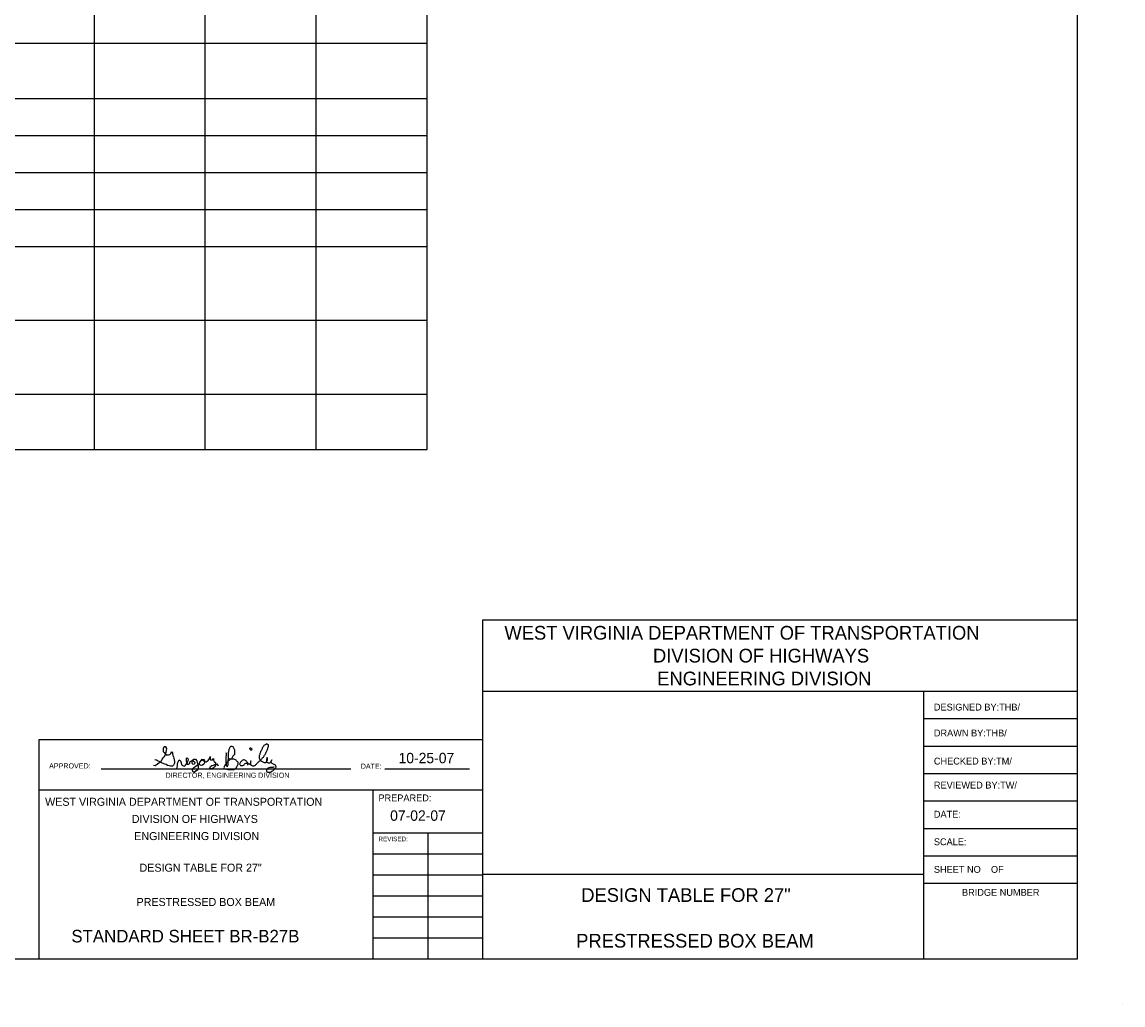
# Model space of a CAD drawing. Extents: x 762.3 to 790.4, y -1210.3 to -1192.2.
# Drawn here: x 780.44 to 790.37, y -1210.35 to -1201.48 of the extents above; entities that cross this region are included whole.
import ezdxf

# ---------------------------------------------------------------- set-up
doc = ezdxf.new("R2010")
doc.units = 0
doc.layers.add('Default', color=7, linetype='Continuous')
doc.layers.add('Level 1', color=7, linetype='Continuous')

msp = doc.modelspace()

# ---------------------------------------------------------------- linework, layer by layer
at = {"layer": 'Default'}
for p, q in [((789.9542, -1192.6096), (789.9542, -1209.9346)), ((781.0909, -1202.1689), (781.0909, -1201.1689)), ((782.0909, -1202.1689), (782.0909, -1201.1689)), ((783.0909, -1202.1689), (783.0909, -1201.1689)), ((784.0909, -1202.1689), (784.0909, -1201.1689)), ((764.5075, -1201.6689), (784.0909, -1201.6689)), ((764.5075, -1202.1689), (784.0909, -1202.1689)), ((781.0909, -1205.3356), (781.0909, -1202.1689)), ((782.0909, -1205.3356), (782.0909, -1202.1689)), ((783.0909, -1205.3356), (783.0909, -1202.1689)), ((784.0909, -1205.3356), (784.0909, -1202.1689)), ((766.2575, -1202.5023), (784.0909, -1202.5023)), ((766.2575, -1202.8356), (784.0909, -1202.8356)), ((764.5075, -1203.1689), (784.0909, -1203.1689)), ((766.2575, -1203.5023), (784.0909, -1203.5023)), ((766.2575, -1204.1689), (784.0909, -1204.1689)), ((764.5075, -1204.8356), (784.0909, -1204.8356)), ((764.5075, -1205.3356), (784.0909, -1205.3356)), ((789.9542, -1206.8755), (784.5917, -1206.8755)), ((784.5917, -1206.8755), (784.5917, -1209.9346)), ((784.5917, -1206.9415), (784.5917, -1206.9415)), ((789.9542, -1206.9415), (789.9542, -1206.9415)), ((788.5682, -1207.519), (784.5917, -1207.519)), ((788.5682, -1207.519), (788.5682, -1209.9346)), ((789.9542, -1207.519), (788.5682, -1207.519)), ((789.9542, -1207.7665), (788.5682, -1207.7665)), ((784.5917, -1207.9546), (780.5905, -1207.9546)), ((780.5905, -1207.9546), (780.5905, -1209.9346)), ((784.5917, -1207.9546), (784.5917, -1207.9546)), ((789.9542, -1208.014), (788.5682, -1208.014)), ((781.152, -1208.2157), (783.4022, -1208.2157)), ((783.7105, -1208.2157), (784.4725, -1208.2157)), ((789.9542, -1208.2615), (788.5682, -1208.2615)), ((783.6017, -1208.4083), (780.5905, -1208.4083)), ((783.6017, -1208.4083), (783.6017, -1209.9346)), ((784.5917, -1208.4083), (783.6017, -1208.4083)), ((789.9542, -1208.509), (788.5682, -1208.509)), ((784.5917, -1208.7961), (783.6017, -1208.7961)), ((784.0967, -1208.7961), (784.0967, -1209.9346)), ((789.9542, -1208.7565), (788.5682, -1208.7565)), ((784.5917, -1208.9858), (783.6017, -1208.9858)), ((789.9542, -1209.004), (788.5682, -1209.004)), ((784.5917, -1209.1756), (783.6017, -1209.1756)), ((788.5682, -1209.169), (784.5917, -1209.169)), ((789.9542, -1209.2515), (788.5682, -1209.2515)), ((784.5917, -1209.3653), (783.6017, -1209.3653)), ((784.5917, -1209.5551), (783.6017, -1209.5551)), ((784.5917, -1209.7448), (783.6017, -1209.7448)), ((789.9542, -1209.9346), (763.5542, -1209.9346)), ((784.5917, -1209.9346), (784.5917, -1209.9346)), ((784.5917, -1209.9346), (784.5917, -1209.9346)), ((789.9542, -1209.9115), (789.9542, -1209.9115)), ((789.9542, -1209.9346), (789.9542, -1209.9346)), ((790.3667, -1210.3471), (790.3667, -1210.3471))]:
    msp.add_line(p, q, dxfattribs=at)
at = {"layer": 'Level 1'}
for points in [[(781.6233, -1208.1826), (781.6383, -1208.1851), (781.648, -1208.1804), (781.6609, -1208.1726), (781.671, -1208.1625), (781.6836, -1208.155), (781.6949, -1208.1437), (781.7011, -1208.1286), (781.7099, -1208.1173), (781.7212, -1208.1073), (781.73, -1208.0947), (781.7363, -1208.0809), (781.7388, -1208.0646), (781.7413, -1208.0495), (781.7426, -1208.0344), (781.7338, -1208.0193), (781.72, -1208.0193), (781.7124, -1208.0306), (781.7099, -1208.0445), (781.7099, -1208.0595), (781.72, -1208.0696), (781.7288, -1208.0821), (781.7413, -1208.0897), (781.7577, -1208.0909), (781.7715, -1208.0884), (781.7803, -1208.0771), (781.7891, -1208.0633), (781.7966, -1208.0683), (781.7941, -1208.0821), (781.7979, -1208.096), (781.8029, -1208.1085), (781.8079, -1208.1211), (781.8104, -1208.1362), (781.8129, -1208.1512), (781.8129, -1208.1663), (781.8041, -1208.1826), (781.7941, -1208.1927), (781.7778, -1208.1927), (781.7652, -1208.1892), (781.7501, -1208.1851), (781.7376, -1208.1776), (781.725, -1208.1744), (781.7112, -1208.1676), (781.6974, -1208.1625), (781.6861, -1208.155), (781.6735, -1208.15), (781.6609, -1208.1449), (781.6496, -1208.1374), (781.6371, -1208.1349)], [(782.2774, -1208.0696), (782.278, -1208.0765), (782.278, -1208.0834), (782.278, -1208.0903), (782.278, -1208.0978), (782.2767, -1208.1047), (782.2755, -1208.1117), (782.2755, -1208.1186), (782.2755, -1208.1255), (782.2755, -1208.1324), (782.2761, -1208.1393), (782.2767, -1208.1462), (782.2767, -1208.1531), (782.2774, -1208.16), (782.2786, -1208.1669), (782.2793, -1208.1745), (782.2799, -1208.1814), (782.2818, -1208.1883), (782.2862, -1208.1933), (782.2899, -1208.199), (782.2918, -1208.192), (782.2943, -1208.1858), (782.2962, -1208.1789), (782.2968, -1208.1719), (782.2968, -1208.165), (782.2968, -1208.1581), (782.2975, -1208.1512), (782.2975, -1208.1443), (782.2981, -1208.1374), (782.2987, -1208.1305), (782.2994, -1208.1236), (782.2994, -1208.1167), (782.2994, -1208.1098), (782.2994, -1208.1029), (782.2994, -1208.096), (782.2994, -1208.089), (782.2994, -1208.0821), (782.3, -1208.0752), (782.3012, -1208.0683), (782.3025, -1208.0608), (782.3044, -1208.0539), (782.3063, -1208.047), (782.3069, -1208.0401), (782.3094, -1208.0338), (782.3119, -1208.0275), (782.3144, -1208.0212), (782.3182, -1208.0149), (782.3245, -1208.0124), (782.3314, -1208.0131), (782.3383, -1208.0149), (782.3427, -1208.02), (782.3458, -1208.0262), (782.3496, -1208.0319), (782.3527, -1208.0382), (782.354, -1208.0451), (782.3546, -1208.052), (782.3546, -1208.0589), (782.3546, -1208.0658), (782.3546, -1208.0727), (782.3546, -1208.0796), (782.3534, -1208.0865), (782.3496, -1208.0922), (782.3446, -1208.0966), (782.3402, -1208.1016), (782.3377, -1208.1079), (782.3339, -1208.1135), (782.3301, -1208.1192), (782.3276, -1208.1255), (782.322, -1208.1292), (782.3157, -1208.1324), (782.31, -1208.1368), (782.3038, -1208.1405), (782.2987, -1208.1449), (782.2937, -1208.15), (782.2899, -1208.1556), (782.2849, -1208.16), (782.2811, -1208.1657), (782.2774, -1208.1713), (782.2723, -1208.177), (782.2686, -1208.1826), (782.2661, -1208.1889), (782.2623, -1208.1946), (782.2598, -1208.2008), (782.2585, -1208.2077), (782.261, -1208.214), (782.2673, -1208.2165), (782.2742, -1208.2172), (782.2811, -1208.2191), (782.2881, -1208.2203), (782.295, -1208.2209), (782.3019, -1208.2209), (782.3094, -1208.2209), (782.3163, -1208.2209), (782.3232, -1208.2209), (782.3301, -1208.2209), (782.337, -1208.2209), (782.3439, -1208.2209), (782.3509, -1208.2209), (782.3559, -1208.2159), (782.3622, -1208.2134), (782.3678, -1208.2096), (782.3735, -1208.2046), (782.376, -1208.1983), (782.3785, -1208.192), (782.3823, -1208.1864), (782.3848, -1208.1801), (782.3867, -1208.1732), (782.3879, -1208.1663), (782.3879, -1208.1594), (782.3835, -1208.1544), (782.3785, -1208.15), (782.3735, -1208.1449), (782.3691, -1208.1393), (782.3628, -1208.1355), (782.3565, -1208.1318), (782.3496, -1208.1305), (782.3427, -1208.1292), (782.3358, -1208.128), (782.3282, -1208.128), (782.3207, -1208.128), (782.3138, -1208.128), (782.3069, -1208.1267), (782.3069, -1208.1267)], [(782.5933, -1208.1362), (782.5971, -1208.1305), (782.6008, -1208.1248), (782.6046, -1208.1192), (782.609, -1208.1142), (782.6146, -1208.1104), (782.619, -1208.1054), (782.6228, -1208.0991), (782.6259, -1208.0928), (782.6303, -1208.0865), (782.6341, -1208.0803), (782.6366, -1208.074), (782.6404, -1208.0671), (782.6435, -1208.0602), (782.6467, -1208.0532), (782.6492, -1208.047), (782.6517, -1208.0407), (782.6542, -1208.0344), (782.6561, -1208.0275), (782.6586, -1208.0212), (782.6599, -1208.0143), (782.6611, -1208.0074), (782.6599, -1208.0005), (782.6555, -1207.9955), (782.6492, -1207.993), (782.6423, -1207.9917), (782.636, -1207.9955), (782.6303, -1207.9992), (782.6241, -1208.0017), (782.619, -1208.0061), (782.6153, -1208.0118), (782.6115, -1208.0174), (782.6065, -1208.0225), (782.6052, -1208.0294), (782.6027, -1208.0357), (782.6002, -1208.0419), (782.5964, -1208.0476), (782.5939, -1208.0539), (782.5901, -1208.0595), (782.5889, -1208.0664), (782.5851, -1208.0721), (782.5839, -1208.079), (782.5813, -1208.0859), (782.5788, -1208.0928), (782.5763, -1208.0991), (782.5763, -1208.106), (782.5763, -1208.1129), (782.5776, -1208.1198), (782.5807, -1208.1261), (782.5832, -1208.133), (782.5864, -1208.1393), (782.5914, -1208.1437), (782.5977, -1208.1462), (782.6033, -1208.1506), (782.6102, -1208.1519), (782.6165, -1208.1556), (782.6228, -1208.1581), (782.6303, -1208.1588), (782.6372, -1208.1588), (782.641, -1208.1531), (782.6448, -1208.1475), (782.6479, -1208.1405), (782.6504, -1208.1336), (782.6511, -1208.1267), (782.6529, -1208.1192), (782.6479, -1208.1148), (782.6454, -1208.1217), (782.6429, -1208.128), (782.6429, -1208.1349), (782.6429, -1208.1418), (782.6429, -1208.1487), (782.6454, -1208.1556), (782.6517, -1208.1594), (782.658, -1208.1619), (782.6649, -1208.1625), (782.6718, -1208.1625), (782.6781, -1208.16), (782.6818, -1208.1537), (782.6862, -1208.1487), (782.6894, -1208.1418), (782.6913, -1208.1349), (782.6881, -1208.1418), (782.6856, -1208.1481), (782.6831, -1208.1544), (782.6856, -1208.1606), (782.6919, -1208.1638), (782.6982, -1208.1669), (782.7026, -1208.1719), (782.7095, -1208.1738), (782.7164, -1208.1763), (782.7208, -1208.1814), (782.7233, -1208.1877), (782.7258, -1208.1939), (782.7258, -1208.2008), (782.7245, -1208.2077), (782.7195, -1208.2121), (782.7158, -1208.2178), (782.7107, -1208.2234), (782.707, -1208.2291), (782.7007, -1208.2335), (782.6957, -1208.2379), (782.6894, -1208.2417), (782.6831, -1208.2454), (782.6774, -1208.2492), (782.6699, -1208.2498), (782.663, -1208.2505), (782.6561, -1208.2505), (782.6498, -1208.2467), (782.646, -1208.241), (782.6448, -1208.2341), (782.6454, -1208.2272), (782.6473, -1208.2203), (782.6511, -1208.214), (782.6555, -1208.209), (782.6617, -1208.2065), (782.668, -1208.204), (782.6749, -1208.2027), (782.6818, -1208.2027), (782.6887, -1208.2015), (782.6957, -1208.2015), (782.7026, -1208.2002), (782.7095, -1208.199), (782.7132, -1208.1977)], [(781.8333, -1208.2165), (781.8371, -1208.2021), (781.839, -1208.1883), (781.8409, -1208.1745), (781.8434, -1208.1606), (781.8484, -1208.1468), (781.8566, -1208.1355), (781.8673, -1208.1437), (781.8735, -1208.1625), (781.8761, -1208.1763), (781.8848, -1208.1864), (781.9031, -1208.1933), (781.9131, -1208.1839), (781.9219, -1208.1726), (781.9301, -1208.1619), (781.9345, -1208.1487), (781.9395, -1208.1355), (781.9376, -1208.1217), (781.9194, -1208.1192), (781.9194, -1208.133), (781.9194, -1208.1468), (781.9213, -1208.1606), (781.9263, -1208.1738), (781.942, -1208.1751), (781.9508, -1208.165), (781.9552, -1208.1512), (781.9677, -1208.1456), (781.9816, -1208.1456), (781.9973, -1208.1575), (781.9929, -1208.1751), (781.9791, -1208.1763), (781.9715, -1208.165), (781.9721, -1208.1506), (781.9765, -1208.1368), (781.9885, -1208.1305), (782.0023, -1208.128), (782.0136, -1208.1443), (782.0174, -1208.1581), (782.0211, -1208.1713), (782.0255, -1208.1845), (782.0274, -1208.1983), (782.0274, -1208.2128), (782.0174, -1208.2297), (782.0067, -1208.2385), (781.9948, -1208.2461), (781.9809, -1208.2467), (781.9753, -1208.2278), (781.9791, -1208.2147), (781.9878, -1208.2046), (781.9975, -1208.1974), (782.0079, -1208.1889), (782.0249, -1208.1789), (782.0387, -1208.1644), (782.0435, -1208.1531), (782.0532, -1208.1405), (782.0613, -1208.1299), (782.0795, -1208.1336), (782.0827, -1208.1475), (782.0827, -1208.1613), (782.0777, -1208.1745), (782.067, -1208.1826), (782.0538, -1208.187), (782.0419, -1208.1807), (782.0393, -1208.1676), (782.0425, -1208.1544), (782.0506, -1208.1431), (782.0632, -1208.138), (782.0814, -1208.1462), (782.0996, -1208.1525), (782.1153, -1208.1424), (782.1235, -1208.1318), (782.1304, -1208.1192), (782.1354, -1208.1054), (782.1354, -1208.1123), (782.1342, -1208.1261), (782.1398, -1208.1387), (782.1562, -1208.1343), (782.165, -1208.1236), (782.1662, -1208.1242), (782.1643, -1208.138), (782.1719, -1208.1506), (782.1819, -1208.16), (782.1825, -1208.1738), (782.1825, -1208.1877), (782.175, -1208.199), (782.165, -1208.2084), (782.1518, -1208.214), (782.1386, -1208.2172), (782.1304, -1208.2065), (782.1392, -1208.1946), (782.1511, -1208.1864), (782.165, -1208.1839), (782.1763, -1208.1763), (782.1957, -1208.1726), (782.2058, -1208.1883), (782.207, -1208.1877)], [(782.4928, -1208.0332), (782.4928, -1208.0401), (782.4978, -1208.0445), (782.5047, -1208.0463), (782.5116, -1208.0457), (782.5129, -1208.0388), (782.5079, -1208.0344), (782.5028, -1208.0294), (782.4959, -1208.0294), (782.4897, -1208.0319), (782.4897, -1208.0363)], [(782.4733, -1208.182), (782.4746, -1208.1751), (782.4746, -1208.1682), (782.4746, -1208.1613), (782.4689, -1208.1562), (782.4639, -1208.1512), (782.4601, -1208.1456), (782.4545, -1208.1418), (782.4488, -1208.138), (782.4426, -1208.1355), (782.4356, -1208.1355), (782.4287, -1208.138), (782.4237, -1208.1424), (782.4181, -1208.1468), (782.413, -1208.1512), (782.4093, -1208.1569), (782.4068, -1208.1632), (782.403, -1208.1688), (782.4005, -1208.1751), (782.4049, -1208.1801), (782.4093, -1208.1851), (782.4168, -1208.187), (782.4237, -1208.187), (782.4306, -1208.187), (782.4369, -1208.1845), (782.4413, -1208.1789), (782.4457, -1208.1738), (782.4501, -1208.1682), (782.4564, -1208.1644), (782.4639, -1208.1644), (782.4714, -1208.165), (782.4777, -1208.1676), (782.484, -1208.1701), (782.4897, -1208.1738), (782.4966, -1208.1738), (782.4984, -1208.1669), (782.5003, -1208.16), (782.501, -1208.1525), (782.501, -1208.1456), (782.4984, -1208.1519), (782.4972, -1208.1588), (782.4972, -1208.1657), (782.4972, -1208.1726), (782.4978, -1208.1795), (782.5041, -1208.1826), (782.5104, -1208.1864), (782.5173, -1208.1883), (782.5242, -1208.1889), (782.5311, -1208.1889), (782.538, -1208.1877), (782.5437, -1208.1839), (782.5474, -1208.1776), (782.5525, -1208.1732), (782.5562, -1208.1669), (782.5613, -1208.1625), (782.5669, -1208.1588), (782.5719, -1208.1537), (782.577, -1208.1487), (782.5826, -1208.1449), (782.5883, -1208.1412), (782.592, -1208.1362)]]:
    msp.add_lwpolyline(points, dxfattribs=at)

# ---------------------------------------------------------------- texts
at = {"layer": 'Default'}
for s, height, p in [('WEST VIRGINIA DEPARTMENT OF TRANSPORTATION', 0.12375, (784.7884, -1207.0508)), ('DIVISION OF HIGHWAYS', 0.12375, (786.1282, -1207.2571)), ('ENGINEERING DIVISION', 0.12375, (786.1667, -1207.4633)), ('DESIGNED BY:THB/', 0.061875, (788.6613, -1207.6904)), ('DRAWN BY:THB/', 0.061875, (788.6613, -1207.9241)), ('10-25-07', 0.09375, (783.8338, -1208.1658)), ('CHECKED BY:TM/', 0.061875, (788.6613, -1208.1776)), ('APPROVED:                                                  ', 0.046406, (780.6826, -1208.2129)), ('DATE:', 0.04641, (783.493, -1208.2157)), ('DIRECTOR, ENGINEERING DIVISION', 0.046406, (781.7318, -1208.2974)), ('REVIEWED BY:TW/', 0.061875, (788.6613, -1208.3941)), ('WEST VIRGINIA DEPARTMENT OF TRANSPORTATION', 0.072188, (780.6464, -1208.5498)), ('PREPARED:', 0.06187, (783.6523, -1208.5093)), ('07-02-07', 0.09375, (783.758, -1208.685)), ('DATE:', 0.06187, (788.6613, -1208.6568)), ('DIVISION OF HIGHWAYS', 0.072188, (781.4279, -1208.7045)), ('ENGINEERING DIVISION', 0.072188, (781.4504, -1208.8592)), ('REVISED:', 0.04125, (783.6523, -1208.8696)), ('SCALE:', 0.06187, (788.6613, -1208.9056)), ('DESIGN TABLE FOR 27"', 0.072188, (781.4978, -1209.1444)), ('SHEET NO    OF', 0.061875, (788.6613, -1209.1545)), ('DESIGN TABLE FOR 27"', 0.12375, (785.4815, -1209.4168)), ('BRIDGE NUMBER', 0.061875, (788.9148, -1209.3619)), ('PRESTRESSED BOX BEAM', 0.072188, (781.4711, -1209.4538)), ('STANDARD SHEET BR-B27B', 0.113437, (780.8831, -1209.7825)), ('PRESTRESSED BOX BEAM', 0.12375, (785.4357, -1209.8293))]:
    msp.add_text(s, height=height, dxfattribs=at).set_placement(p)

doc.saveas('drawing.dxf')
